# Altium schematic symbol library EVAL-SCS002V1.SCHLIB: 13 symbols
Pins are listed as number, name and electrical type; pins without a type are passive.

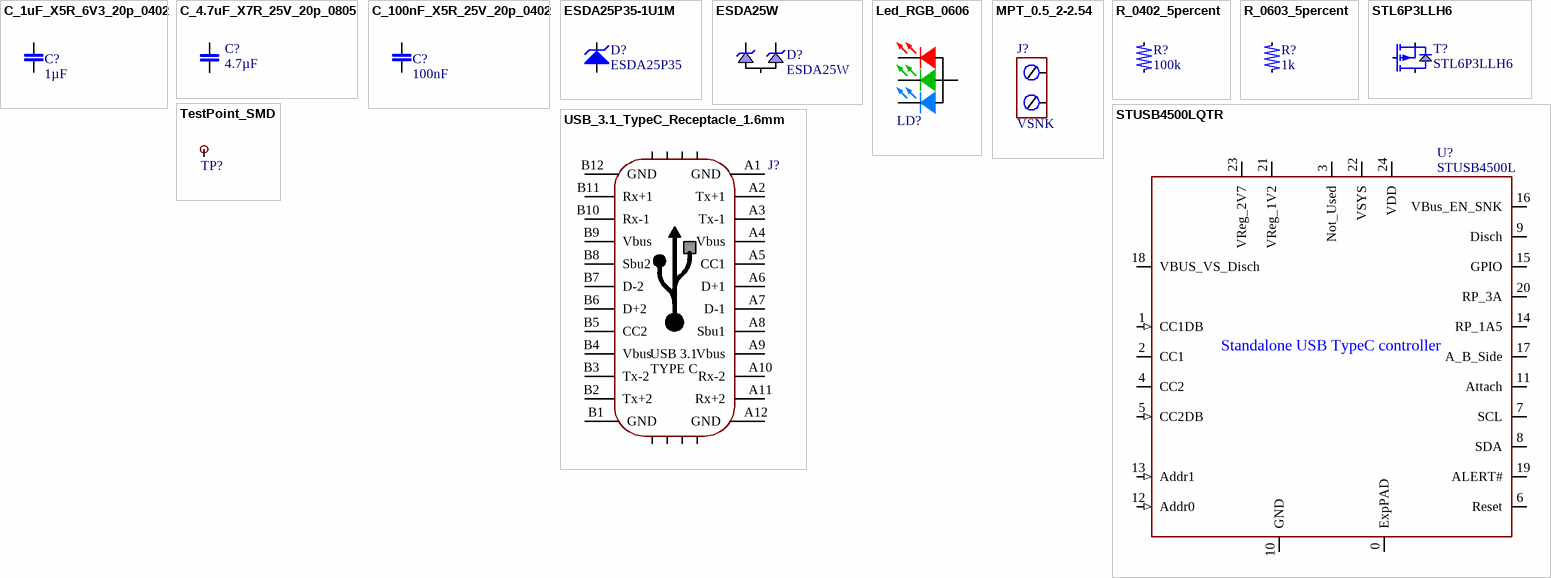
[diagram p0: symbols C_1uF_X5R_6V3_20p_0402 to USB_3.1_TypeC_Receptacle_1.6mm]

## C_1uF_X5R_6V3_20p_0402
designator C?, comment 1µF
Capacitor 1µF X5R 6V3 20% 0402; Manufacturer: Würth Elektronik; Manufacturer’s ordering code: 885012105006; Order Code RS: 839-1641
footprint CAPC1005N (Chip Capacitor, Body 1.0x0.5mm, IPC Medium Density)
pins: 1, 2

## C_4.7uF_X7R_25V_20p_0805
designator C?, comment 4.7µF
Capacitor 4.7µF X7R 25V 20% 0805; Manufacturer: Würth Elektronik; Manufacturer’s ordering code: 885012107018
footprint CAPC2012N (Chip Capacitor, Body 2.0x1.3mm, IPC Medium Density)
pins: 1, 2

## C_100nF_X5R_25V_20p_0402
designator C?, comment 100nF
Capacitor 100nF X5R 25V 20% 0402; Manufacturer: Würth Elektronik; Manufacturer’s ordering code: 885012105018; Order Code RS: 839-1685
footprint CAPC1005N (Chip Capacitor, Body 1.0x0.5mm, IPC Medium Density)
pins: 1, 2

## ESDA25P35-1U1M
designator D?, comment ESDA25P35
High power transient voltage suppressor Vbr = 24.6V; Manufacturer: STMicroelectronics; Manufacturer’s ordering code: ESDA25P35-1U1M; Value: 22V; Order Code RS: 163-9774
footprint QFN1610 (QFN 1610)
pins: 1 K, 2 A

## ESDA25W
designator D?
Dual Transil Array For ESD Protection in SOT323 Vbr = 25V; Manufacturer: STMicroelectronics; Order Code RS: 250-117; Value: 25V TRANSIL SOT323
footprint SOT323-3L (SOT323, 3-Leads, Body 2.2x2.4mm (max), Pitch 0.65mm, IPC Medium Density)
pins: 1 K1, 2 K2 (power), 3 A

## Led_RGB_0606
designator LD?, comment RGB  (value not drawn)
RGB Led 1.6 x 1.6 mm Diffused; Manufacturer: Würth Elektronik; Manufacturer’s ordering code: 150066M153000
footprint LED_0606_RGB_WURTH (Chip; Body 1.6 x 1.6 mm (LxW typ) WURTH)
pins: A, BK, GK, RK

## MPT_0.5_2-2.54
designator J?, comment VSNK
2 way PCB vertical mount SCREW terminal, 2.54mm; Manufacturer: Würth Elektronik; Manufacturer’s ordering code: 691210910002; Alternate Manufacturer: Phoenix Contact; Alternate Manufacturer Code: MPT 0.5/2-2.54; misc: JK308-2.54-2P
footprint MPT_0.5_2-2.54 (Screw  PCB terminal block, 2 positions 2.54mm pitch)
pins: 1, 2

## R_0402_5percent
designator R?, comment 100k
5% 0402 SMD resistor
footprint RESC1005N (Chip Resistor, Body 1.0x0.5mm, IPC Medium Density)
pins: 1, 2

## R_0603_5percent
designator R?, comment 1k
5% 0603 SMD resistor
footprint RESC1608N (Chip Resistor, Body 1.6x0.8mm, IPC Medium Density)
pins: 1, 2

## STL6P3LLH6
designator T?
P-channel 40 V, 0.0175 Ω typ.,8 A, STripFET™ F6  Power MOSFET in a PowerFLAT™ 3.3 x 3.3 package; Manufacturer: STMicroelectronics; Part Number: P-channel 30 V, 0.024 Ohm typ., 6 A STripFET H6 Power MOSFET in a PowerFLAT 3.3 x 3.3 package
footprint PowerFLAT_3.3x3.3_F (PowerFLAT™ 3.3 x 3.3 type F)
pins: 1 S1, 2 S2, 3 S3, 4 G, 5 D1, 6 D2, 7 D3, 8 D4

## STUSB4500LQTR
designator U?, comment STUSB4500L
Standalone USB PD controller  with SINK auto-run mode in QFN24 4x4mm; Manufacturer: STMicroelectronics; Manufacturer’s ordering code: STUSB4500QTR
footprint QFN24 - 4X4mm - pitch 0.5mm - ExposedPAD
pins: 0 ExpPAD, 1 CC1DB (in), 2 CC1 (io), 3 Not_Used, 4 CC2 (io), 5 CC2DB (in), 6 Reset, 7 SCL, 8 SDA, 9 Disch (oc), 10 GND, 11 Attach (oc), 12 Addr0 (in), 13 Addr1 (in), 14 RP_1A5 (oc), 15 GPIO (oc), 16 VBus_EN_SNK (oc), 17 A_B_Side (oc), 18 VBUS_VS_Disch, 19 ALERT# (oc), 20 RP_3A (oc), 21 VReg_1V2, 22 VSYS, 23 VReg_2V7, 24 VDD

## TestPoint_SMD
designator TP?, comment TestPoint  (value not drawn)  (no BOM)
TestPoint_SMD
footprint TestPoint_SMD_1.27mm
pins: 0

## USB_3.1_TypeC_Receptacle_1.6mm
designator J?  (value not drawn)
USB 3.1 Type C Receptacle Horizontal THR WR-COM 1.6mm PCB thickness; Manufacturer’s ordering code: 632723300011; Manufacturer: Würth Elektronik
footprint USB3 C - SMT et T - H - F - WURTH - 632723X00011 (USB3 type C - montage sur CI - Femmelle - Angle droit - Composant Certifié (x=1 -> PCB height= 1mm TID : 5,200,000,115 // x=3 -> PCB height= 1mm TID : 5,200,000,116))
pins: A1 GND, A2 Tx+1, A3 Tx-1, A4 Vbus, A5 CC1, A6 D+1, A7 D-1, A8 Sbu1, A9 Vbus, A10 Rx-2, A11 Rx+2, A12 GND, B1 GND, B2 Tx+2, B3 Tx-2, B4 Vbus, B5 CC2, B6 D+2, B7 D-2, B8 Sbu2, B9 Vbus, B10 Rx-1, B11 Rx+1, B12 GND, G1, G2, G3, G4, G5, G6, G7, G8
